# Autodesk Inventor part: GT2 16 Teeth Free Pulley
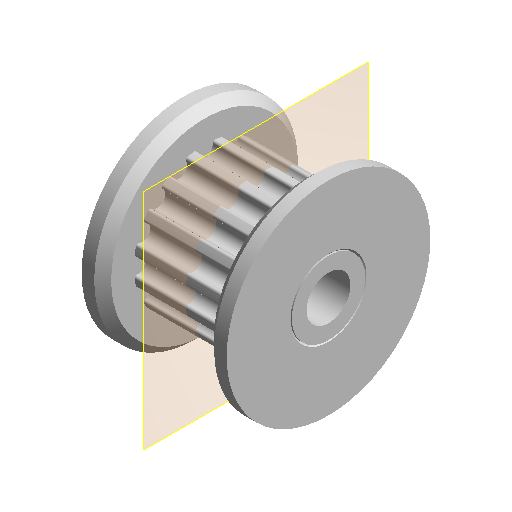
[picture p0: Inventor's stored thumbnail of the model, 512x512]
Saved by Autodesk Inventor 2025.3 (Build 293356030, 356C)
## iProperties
Created: 2017-11
Part Number: GT2 16 Teeth Free Pulley
Material: Generico
Document SubType Name: Modeling
Designer: Administrator
Appearance: Generic
Title: GT2 16 Teeth Free Pulley v3
Author: Administrator
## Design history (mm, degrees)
feature "Body1"
node "Piano di lavoro1"
body "Solid1"
